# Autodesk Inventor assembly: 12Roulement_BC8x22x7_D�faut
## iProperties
Created: 2011-01
Part Number: 12Roulement_BC8x22x7_D�faut
Document SubType Name: Assembly
Designer: eric
Mass: 1.54909 g
Surface Area: 21.7227 cm^2
Volume: 1.54909 cm^3
Density: 1 g/cm^3
Author: eric
